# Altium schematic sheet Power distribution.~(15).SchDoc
size A3; SheetNumber: 4; SheetTotal: 4
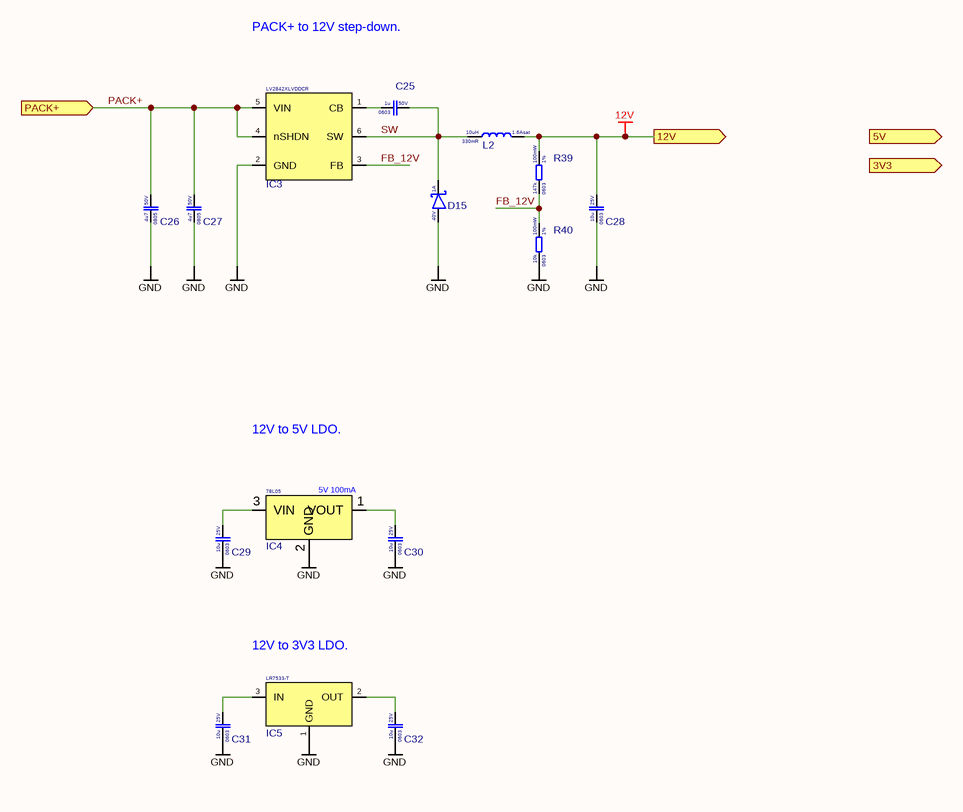
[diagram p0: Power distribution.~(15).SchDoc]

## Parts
C25  Voltage Rating: 50V  Case Code (Imperial): 0603  Capacitance: 1u  [CAP 0603]  (hidden comment: CL10A105KB8NNNC)
C26  Voltage Rating: 50V  Case Code (Imperial): 0805  Capacitance: 4u7  [Cap_0805]  (hidden comment: CL21A475KBQNNNE)
C27  Voltage Rating: 50V  Case Code (Imperial): 0805  Capacitance: 4u7  [Cap_0805]  (hidden comment: CL21A475KBQNNNE)
C28  Voltage Rating: 25V  Case Code (Imperial): 0603  Capacitance: 10u  [CAP 0603]  (hidden comment: CL10A106MA8NRNC)
C29  Voltage Rating: 25V  Case Code (Imperial): 0603  Capacitance: 10u  [CAP 0603]  (hidden comment: CL10A106MA8NRNC)
C30  Voltage Rating: 25V  Case Code (Imperial): 0603  Capacitance: 10u  [CAP 0603]  (hidden comment: CL10A106MA8NRNC)
C31  Voltage Rating: 25V  Case Code (Imperial): 0603  Capacitance: 10u  [CAP 0603]  (hidden comment: CL10A106MA8NRNC)
C32  Voltage Rating: 25V  Case Code (Imperial): 0603  Capacitance: 10u  [CAP 0603]  (hidden comment: CL10A106MA8NRNC)
D15  Forward Current: 1A  Reverse Voltage: 40V  [SOD-323]  (hidden comment: 1N5819WS)
IC3  LV2842XLVDDCR  [SOT-23-6]
IC4  78L05  [SOT-89-3]
IC5  LR7533-T  [SOT-23 123]
L2  Resistance: 330mR  Saturation current: 1.6Asat  Inductance: 10uH  [IND 1008]  (hidden comment: FTC252012S100MBCA)
R39  Resistance Tolerance: 1%  Resistance: 147k  Power Rating: 100mW  Case Code (Imperial): 0603  [RES_0603]  (hidden comment: 0603WAF1473T5E)
R40  Resistance Tolerance: 1%  Resistance: 10k  Power Rating: 100mW  Case Code (Imperial): 0603  [RES_0603]  (hidden comment: 0603WAF1002T5E)

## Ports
3V3 (out, see Arhitecture[5C]), 5V (out, see Arhitecture[5C]), 12V (out, see Arhitecture[5C], Charger[1A]), PACK+ (in, see Arhitecture[6C], Battery level indicator[3B], Charger[8A])

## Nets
12V: C28.2 L2.2 R39.2 ; port 12V
GND: C26.1 C27.1 C28.1 C29.1 C30.1 C31.1 C32.1 D15.A IC3.2(GND) IC4.2(GND) IC5.1(GND) R40.1
FB_12V: IC3.3(FB) R39.1 R40.2
PACK+: C26.2 C27.2 IC3.4(nSHDN) IC3.5(VIN) ; port PACK+
SW: C25.2 D15.K IC3.6(SW) L2.1
NetC25_1: C25.1 IC3.1(CB)
NetC29_2: C29.2 IC4.3(VIN)
NetC30_2: C30.2 IC4.1(VOUT)
NetC31_2: C31.2 IC5.3(IN)
NetC32_2: C32.2 IC5.2(OUT)

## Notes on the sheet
- PACK+ to 12V step-down.
- 12V to 5V LDO.
- (near IC5) 12V to 3V3 LDO.

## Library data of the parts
C25 = CL10A105KB8NNNC: Cap 1uF 50V 0603 X5R; Manufacturer: Samsung
C26 C27 = CL21A475KBQNNNE: Cap 4.7uF 50V 0805 X5R; Manufacturer: Samsung
C28-C32 = CL10A106MA8NRNC: Cap 10uF 25V 0603 X5R; Manufacturer: Samsung
D15 = 1N5819WS: Schottky 40V 1A 600mVf SOD-323; Manufacturer: Guangdong Hottech
IC3 = LV2842XLVDDCR: Step-down converter 4~40Vin 600mAout Adjustible SOT23-6; Manufacturer: Texas Instruments
IC4 = 78L05: LDO 5V 100mA 30Vin; Manufacturer: UMW
IC5 = LR7533-T: LDO 24Vin 3.3Vout fixed; Manufacturer: LR
L2 = FTC252012S100MBCA: Inductor 10uH 1.6Asat 330mR; Manufacturer: cjiang
R39 = 0603WAF1473T5E: Res 147k 0603 1% 100mW 75V; Manufacturer: Uni-Royal
R40 = 0603WAF1002T5E: Res 10k 0603 1% 100mW 75V; Manufacturer: Uni-Royal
